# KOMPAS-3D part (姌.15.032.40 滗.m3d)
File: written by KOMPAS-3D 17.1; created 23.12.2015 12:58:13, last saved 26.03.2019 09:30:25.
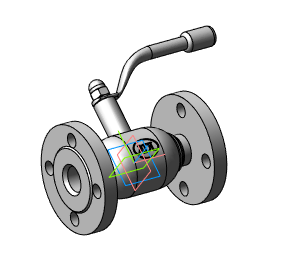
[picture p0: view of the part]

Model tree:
1. Операция без истории:4  (labels: Сталь 20  ГОСТ 1050-88)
